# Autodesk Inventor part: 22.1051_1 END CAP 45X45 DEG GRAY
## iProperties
Created: 2007-01
Part Number: 22.1051_1 END CAP 45X45 DEG GRAY
Document SubType Name: Modeling
Designer: Andy Moles
Material: ABS Plastic
Density: 1.06 g/cm^3
Author: Andy Moles
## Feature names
1. Extrusion1
2. Fillet1
3. Fillet2
4. Fillet3
5. Extrusion2
6. Fillet4
